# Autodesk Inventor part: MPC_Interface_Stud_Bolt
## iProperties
Shininess: 64.0
Length Units: 11269
Angle Units: 11279
Time Units: 11290
Mass Units: 11283
Length Display Precision: 3
Angle Display Precision: 2
Compacted: True
Part Number: MPC_Interface_Stud_Bolt
Document SubType Name: Modeling
Created: 2004-08
Material: Stainless Steel, Austenitic
Designer: John Blackburn
Manufacturer: Standard
Standards Organization: Custom
Density: 0.0
Volumn: 0.0
Area: 0.0
PropertySet Name: Model Information
Control State: 0
Master: False
Checked Out: False
Author: John Blackburn
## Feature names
1. Extrusion1
2. Chamfer1
